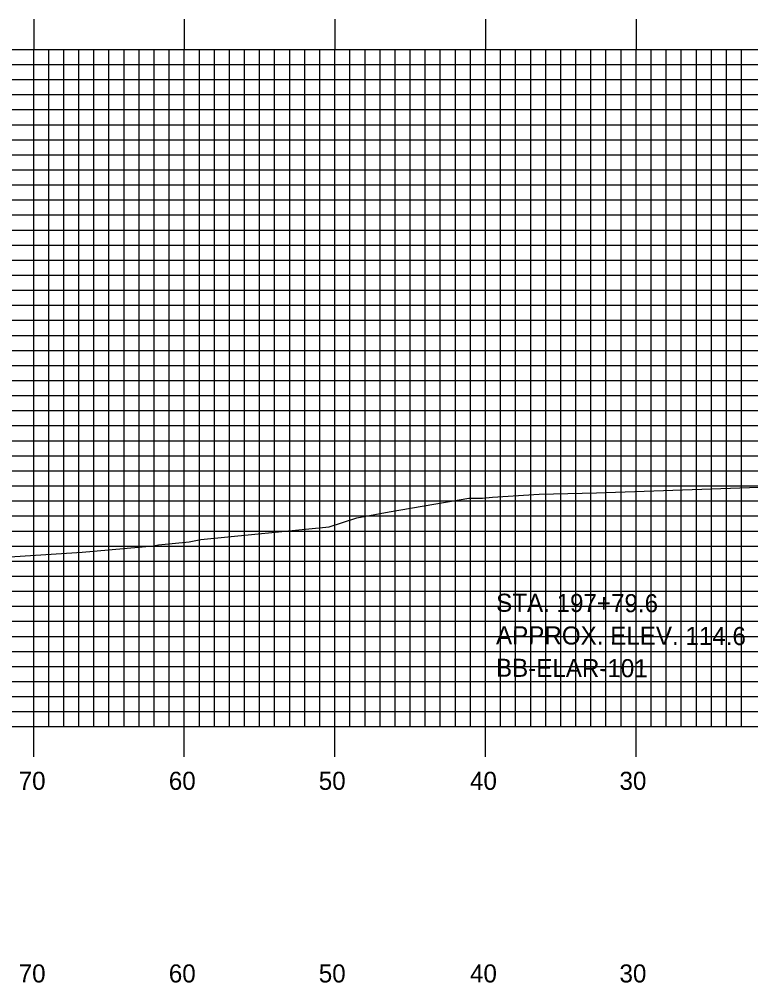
# Model space of a CAD drawing. Extents: x 1790124 to 1790467, y 442591 to 442811.
# Drawn here: x 1790218.7 to 1790267.3, y 442656.6 to 442720.7 of the extents above; entities that cross this region are included whole.
import ezdxf

# ---------------------------------------------------------------- set-up
doc = ezdxf.new("R2010")
doc.units = 0
for name, color, linetype in [('BORING - REFUSAL', 7, 'Continuous'), ('H_V ANNOTATION', 7, 'Continuous'), ('MAJOR', 7, 'Continuous'), ('MINOR', 7, 'Continuous'), ('S_Roadway_Centerline', 7, 'Continuous')]:
    doc.layers.add(name, color=color, linetype=linetype)

msp = doc.modelspace()

# ---------------------------------------------------------------- linework, layer by layer
at = {"layer": 'MAJOR'}
for p, q in [((1790219.696, 442720.669), (1790219.696, 442718.665)), ((1790229.696, 442720.669), (1790229.696, 442718.665)), ((1790239.696, 442720.669), (1790239.696, 442718.665)), ((1790249.696, 442720.669), (1790249.696, 442718.665)), ((1790259.696, 442720.669), (1790259.696, 442718.665)), ((1790149.696, 442718.665), (1790429.696, 442718.665)), ((1790149.696, 442718.665), (1790429.696, 442718.665)), ((1790219.696, 442673.665), (1790219.696, 442718.665)), ((1790229.696, 442673.665), (1790229.696, 442718.665)), ((1790239.696, 442673.665), (1790239.696, 442718.665)), ((1790249.696, 442673.665), (1790249.696, 442718.665)), ((1790259.696, 442673.665), (1790259.696, 442718.665)), ((1790149.696, 442713.665), (1790429.696, 442713.665)), ((1790149.696, 442708.665), (1790429.696, 442708.665)), ((1790149.696, 442703.665), (1790429.696, 442703.665)), ((1790149.696, 442698.665), (1790429.696, 442698.665)), ((1790149.696, 442693.665), (1790429.696, 442693.665)), ((1790149.696, 442688.665), (1790429.696, 442688.665)), ((1790149.696, 442683.665), (1790429.696, 442683.665)), ((1790149.696, 442678.665), (1790429.696, 442678.665)), ((1790149.696, 442673.665), (1790429.696, 442673.665)), ((1790149.696, 442673.665), (1790429.696, 442673.665)), ((1790219.696, 442671.661), (1790219.696, 442673.665)), ((1790229.696, 442671.661), (1790229.696, 442673.665)), ((1790239.696, 442671.661), (1790239.696, 442673.665)), ((1790249.696, 442671.661), (1790249.696, 442673.665)), ((1790259.696, 442671.661), (1790259.696, 442673.665))]:
    msp.add_line(p, q, dxfattribs=at)
at = {"layer": 'MINOR'}
for p, q in [((1790220.696, 442673.665), (1790220.696, 442718.665)), ((1790221.696, 442673.665), (1790221.696, 442718.665)), ((1790222.696, 442673.665), (1790222.696, 442718.665)), ((1790223.696, 442673.665), (1790223.696, 442718.665)), ((1790224.696, 442673.665), (1790224.696, 442718.665)), ((1790225.696, 442673.665), (1790225.696, 442718.665)), ((1790226.696, 442673.665), (1790226.696, 442718.665)), ((1790227.696, 442673.665), (1790227.696, 442718.665)), ((1790228.696, 442673.665), (1790228.696, 442718.665)), ((1790230.696, 442673.665), (1790230.696, 442718.665)), ((1790231.696, 442673.665), (1790231.696, 442718.665)), ((1790232.696, 442673.665), (1790232.696, 442718.665)), ((1790233.696, 442673.665), (1790233.696, 442718.665)), ((1790234.696, 442673.665), (1790234.696, 442718.665)), ((1790235.696, 442673.665), (1790235.696, 442718.665)), ((1790236.696, 442673.665), (1790236.696, 442718.665)), ((1790237.696, 442673.665), (1790237.696, 442718.665)), ((1790238.696, 442673.665), (1790238.696, 442718.665)), ((1790240.696, 442673.665), (1790240.696, 442718.665)), ((1790241.696, 442673.665), (1790241.696, 442718.665)), ((1790242.696, 442673.665), (1790242.696, 442718.665)), ((1790243.696, 442673.665), (1790243.696, 442718.665)), ((1790244.696, 442673.665), (1790244.696, 442718.665)), ((1790245.696, 442673.665), (1790245.696, 442718.665)), ((1790246.696, 442673.665), (1790246.696, 442718.665)), ((1790247.696, 442673.665), (1790247.696, 442718.665)), ((1790248.696, 442673.665), (1790248.696, 442718.665)), ((1790250.696, 442673.665), (1790250.696, 442718.665)), ((1790251.696, 442673.665), (1790251.696, 442718.665)), ((1790252.696, 442673.665), (1790252.696, 442718.665)), ((1790253.696, 442673.665), (1790253.696, 442718.665)), ((1790254.696, 442673.665), (1790254.696, 442718.665)), ((1790255.696, 442673.665), (1790255.696, 442718.665)), ((1790256.696, 442673.665), (1790256.696, 442718.665)), ((1790257.696, 442673.665), (1790257.696, 442718.665)), ((1790258.696, 442673.665), (1790258.696, 442718.665)), ((1790260.696, 442673.665), (1790260.696, 442718.665)), ((1790261.696, 442673.665), (1790261.696, 442718.665)), ((1790262.696, 442673.665), (1790262.696, 442718.665)), ((1790263.696, 442673.665), (1790263.696, 442718.665)), ((1790264.696, 442673.665), (1790264.696, 442718.665)), ((1790265.696, 442673.665), (1790265.696, 442718.665)), ((1790266.696, 442673.665), (1790266.696, 442718.665)), ((1790149.696, 442717.665), (1790429.696, 442717.665)), ((1790149.696, 442716.665), (1790429.696, 442716.665)), ((1790149.696, 442715.665), (1790429.696, 442715.665)), ((1790149.696, 442714.665), (1790429.696, 442714.665)), ((1790149.696, 442712.665), (1790429.696, 442712.665)), ((1790149.696, 442711.665), (1790429.696, 442711.665)), ((1790149.696, 442710.665), (1790429.696, 442710.665)), ((1790149.696, 442709.665), (1790429.696, 442709.665)), ((1790149.696, 442707.665), (1790429.696, 442707.665)), ((1790149.696, 442706.665), (1790429.696, 442706.665)), ((1790149.696, 442705.665), (1790429.696, 442705.665)), ((1790149.696, 442704.665), (1790429.696, 442704.665)), ((1790149.696, 442702.665), (1790429.696, 442702.665)), ((1790149.696, 442701.665), (1790429.696, 442701.665)), ((1790149.696, 442700.665), (1790429.696, 442700.665)), ((1790149.696, 442699.665), (1790429.696, 442699.665)), ((1790149.696, 442697.665), (1790429.696, 442697.665)), ((1790149.696, 442696.665), (1790429.696, 442696.665)), ((1790149.696, 442695.665), (1790429.696, 442695.665)), ((1790149.696, 442694.665), (1790429.696, 442694.665)), ((1790149.696, 442692.665), (1790429.696, 442692.665)), ((1790149.696, 442691.665), (1790429.696, 442691.665)), ((1790149.696, 442690.665), (1790429.696, 442690.665)), ((1790149.696, 442689.665), (1790429.696, 442689.665)), ((1790149.696, 442687.665), (1790429.696, 442687.665)), ((1790149.696, 442686.665), (1790429.696, 442686.665)), ((1790149.696, 442685.665), (1790429.696, 442685.665)), ((1790149.696, 442684.665), (1790429.696, 442684.665)), ((1790149.696, 442682.665), (1790429.696, 442682.665)), ((1790149.696, 442681.665), (1790429.696, 442681.665)), ((1790149.696, 442680.665), (1790429.696, 442680.665)), ((1790149.696, 442679.665), (1790429.696, 442679.665)), ((1790149.696, 442677.665), (1790429.696, 442677.665)), ((1790149.696, 442676.665), (1790429.696, 442676.665)), ((1790149.696, 442675.665), (1790429.696, 442675.665)), ((1790149.696, 442674.665), (1790429.696, 442674.665))]:
    msp.add_line(p, q, dxfattribs=at)
at = {"layer": 'S_Roadway_Centerline'}
msp.add_lwpolyline([(1790213.958, 442684.693), (1790222.913, 442685.249), (1790227.648, 442685.681), (1790227.983, 442685.739), (1790230.014, 442685.947), (1790230.789, 442686.108), (1790239.313, 442686.945), (1790241.157, 442687.55), (1790243.301, 442687.948), (1790248.597, 442688.848), (1790249.499, 442688.856), (1790250.162, 442688.906), (1790253.265, 442689.116), (1790257.058, 442689.207), (1790269.136, 442689.631)], dxfattribs=at)

# ---------------------------------------------------------------- texts
at = {"layer": 'BORING - REFUSAL'}
for s, p in [('STA. 197+79.6', (1790250.401, 442681.299)), ('APPROX. ELEV. 114.6', (1790250.394, 442679.139)), ('BB-ELAR-101', (1790250.387, 442676.979))]:
    msp.add_text(s, height=1.2, rotation=359.81416, dxfattribs=at).set_placement(p)
at = {"layer": 'H_V ANNOTATION'}
for s, p in [('70', (1790218.7, 442669.465)), ('60', (1790228.668, 442669.465)), ('50', (1790238.625, 442669.465)), ('40', (1790248.668, 442669.465)), ('30', (1790258.593, 442669.465)), ('70', (1790218.7, 442656.665)), ('60', (1790228.668, 442656.665)), ('50', (1790238.625, 442656.665)), ('40', (1790248.668, 442656.665)), ('30', (1790258.593, 442656.665))]:
    msp.add_text(s, height=1.2, dxfattribs=at).set_placement(p)

doc.saveas('drawing.dxf')
